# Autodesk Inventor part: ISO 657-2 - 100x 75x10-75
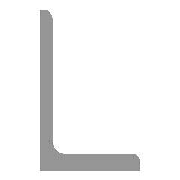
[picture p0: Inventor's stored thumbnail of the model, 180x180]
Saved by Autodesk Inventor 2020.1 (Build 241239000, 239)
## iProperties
Created: 2019-01
Part Number: ISO 657-2 - 100x 75x10-75
Material: Stahl, weich
Description: Warmgewalzte Stahlprofile - Teil 2: ungleichschenklig
Document SubType Name: Modeling
Standard: ISO 657-2
Designer: lutzd
Standard Revision: Hot-rolled steel sections - Part 2: Unequal-leg angles 1989-08-01
Standards Organization: ISO
Language: de-DE
Size Designation: 100x 75x10-75
Categories: <MemberInstance><Categories><Category DisplayName="Profile" InternalName="089c4875-fa83-4c05-b084-43b9cc11f5ed" Mnemonic="GRDR"><CategoryParameter DisplayName="
Stock Number: 100x 75x10
Mass: 919.772 g
Surface Area: 291.349 cm^2
Volume: 117.168 cm^3
Density: 7.85 g/cm^3
Appearance: Semi-Polished(8)
IsCustomPart: 1
G_L: 75,000 mm
Mass: 0,92 kg
VLT_Material: Stahl, weich
Dimensions: 100x75x75 mm
Author: lutzd
Revision Number: -
Title: Warmgewalzte Stahlprofile - Teil 2: ungleichschenklig
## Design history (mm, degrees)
node "Startebene"
node "Endebene"
sketch "Skizze2"
  geometry: L1 (-9.5, 59.1)-(-9.5, -11.9); L2 (-19.5, 68.1)-(-18.5, 68.1); L3 (-19.5, -31.9)-(-19.5, 68.1); L4 (55.5, -31.9)-(-19.5, -31.9); L5 (55.5, -30.9)-(55.5, -31.9); L6 (0.5, -21.9)-(46.5, -21.9); L7 (0, 60.994)-(0, -10.166) reference; L8 (-6.166, 0)-(36.994, 0) reference; A1 r 10 centre (0.5, -11.9) between (-9.5, -11.9) and (0.5, -21.9); A2 r 9 centre (-18.5, 59.1) between (-9.5, 59.1) and (-18.5, 68.1); A3 r 9 centre (46.5, -30.9) between (55.5, -30.9) and (46.5, -21.9); 3 further points
  constraints: 12 end point, 6 point on circle, 6 point on line, 6 tangent, 3 centre point, 3 horizontal, 3 vertical, 1 equal radius
  dimensions: "d4" = 75 distance of L4.start L3.start (= b); "d6" = 100 distance of L3.start L2.start (= ParH); "d8" = 10 distance of point (55.5, -21.9) L4.start (= ParT); "d10" = 10 distance of L2.start point (-9.5, 68.1) (= ParT); "d17" = 10 radius of A1 (= R); "d18" = 9 radius of A2 (= R1); "d19" = 31.9 distance between parallel lines of L8 L4 (= ex); "d20" = 19.5 distance between parallel lines of L3 L7 (= ey)
extrude "Körper" new body sketch "Skizze2" stored distance "d11" = 75 (= G_L); taper "d12" = 0 deg
node "Driven Length"
  sketch "Sketch3"
    geometry: L1 (0, 0)-(10, 0) reference
    constraints: 2 end point, 1 horizontal
  workplane "Work Plane10"
  sketch "Sketch4"
    geometry: L1 (-2, 0)-(12, 0) reference; L2 (-2, 75)-(12, 75) reference
    dimensions: "d24" = 75 distance between parallel lines of L1 L2 (derived)
sketch "Skizze5"
  geometry: L1 (75, -20)-(0, -20) reference; 3 further points
  constraints: 1 midpoint, 1 vertical alignment
  dimensions: "d25" = 75 distance from line of L1 point (37.5, 55)
hole "Bohrung1" sketch "Skizze5" at (37.5, 55) diameter "d26" = 13.5; stored, may be unused: countersink angle "d30" = 90 deg, drill point angle "d32" = 118 deg; dims "d27" = 20, "d28" = 20, "d29" = 13, "d31" = 8
sketch "Skizze6"
  geometry: L1 (-16, 63)-(-16, 47); L2 (-20.5, 63)-(-20.5, 47); L3 (-11.5, 47)-(-11.5, 63); L4 (9, 75)-(9, 0) reference; L5 (-16, 28)-(-16, 12); L6 (-20.5, 28)-(-20.5, 12); L7 (-11.5, 12)-(-11.5, 28); A1 r 4.5 centre (-16, 63) between (-11.5, 63) and (-20.5, 63); A2 r 4.5 centre (-16, 47) between (-20.5, 47) and (-11.5, 47); A3 r 4.5 centre (-16, 28) between (-11.5, 28) and (-20.5, 28); A4 r 4.5 centre (-16, 12) between (-20.5, 12) and (-11.5, 12); 4 further points
  constraints: 16 end point, 8 point on circle, 8 tangent, 4 centre point, 3 midpoint, 2 parallel, 2 vertical, 1 collinear
  dimensions: "d33" = 25 distance between parallel lines of L4 L1; "d34" = 4.5 radius of A1; "d35" = 16 distance of L1.start L1.end; "d36" = 4.5 radius of A3; "d37" = 16 distance of L5.start L5.end (= d35); "d38" = 35 distance of point (-16, 20) point (-16, 55); "d39" = 17.5 vertical distance of point (-16, 55) point (9, 37.5) (= 0.5 x d38)
extrude "Extrusion2" cut sketch "Skizze6" extent not by distance; stored distance "d40" = 90; taper "d41" = 0 deg
workplane "Arbeitsebene11"
workplane "Arbeitsebene12"
body "Solid1"
other parameters: "b" = 75 [user parameter; used in 1 equation term], "ParT" = 10 [user parameter; used in 2 equation terms], "R1" = 9 [user parameter; used in 1 equation term], "G_L" = 75 (= d24) [user parameter; used in 1 equation term], "ParH" = 100 [user parameter; used in 1 equation term], "R" = 10 [user parameter; used in 1 equation term], "d7" = 4 (derived), "d9" = 4 (derived), "ey" = 19.5 [user parameter; used in 1 equation term], "ex" = 31.9 [user parameter; used in 1 equation term], "G_OFFSET_START" = 0 [user parameter; used in 1 equation term], "G_OFFSET_END" = 0 [user parameter; used in 1 equation term], "d21" = 0 (computed from G_OFFSET_START), "d22" = 75 (= G_OFFSET_END + B_L), "B_L" = 75 [user parameter; used in 1 equation term], "d23" = 90 deg
